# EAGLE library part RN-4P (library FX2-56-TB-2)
Widerstandsnetzwerk 4 Parallel
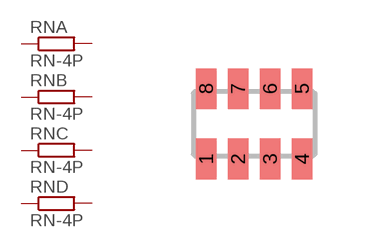
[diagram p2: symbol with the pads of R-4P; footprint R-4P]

Designator prefix RN; gates A=R-EU B=R-EU C=R-EU D=R-EU

## RN-4P1206  [R-4P]
1  A:1  pas
2  B:1  pas
3  C:1  pas
4  D:1  pas
5  D:2  pas
6  C:2  pas
7  B:2  pas
8  A:2  pas

## Footprint R-4P (pad centres in mm)
Widerstandsnetzwerk, 4 parallel, SMD 1206
smd 0.508 x 1.016: 1 -1.2,-0.88; 2 -0.4,-0.88; 3 0.4,-0.88; 4 1.2,-0.88; 5 1.2,0.88; 6 0.4,0.88; 7 -0.4,0.88; 8 -1.2,0.88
